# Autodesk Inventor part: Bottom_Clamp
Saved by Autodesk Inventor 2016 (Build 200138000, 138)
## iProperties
Created: 2016-03
Part Number: Bottom_Clamp
Material: Generic
Document SubType Name: Modeling
Designer: bongo_000
Density: 1 g/cm^3
Appearance: Default
Author: bongo_000
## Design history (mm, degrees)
feature "SOLID1"
body "Solid1"
